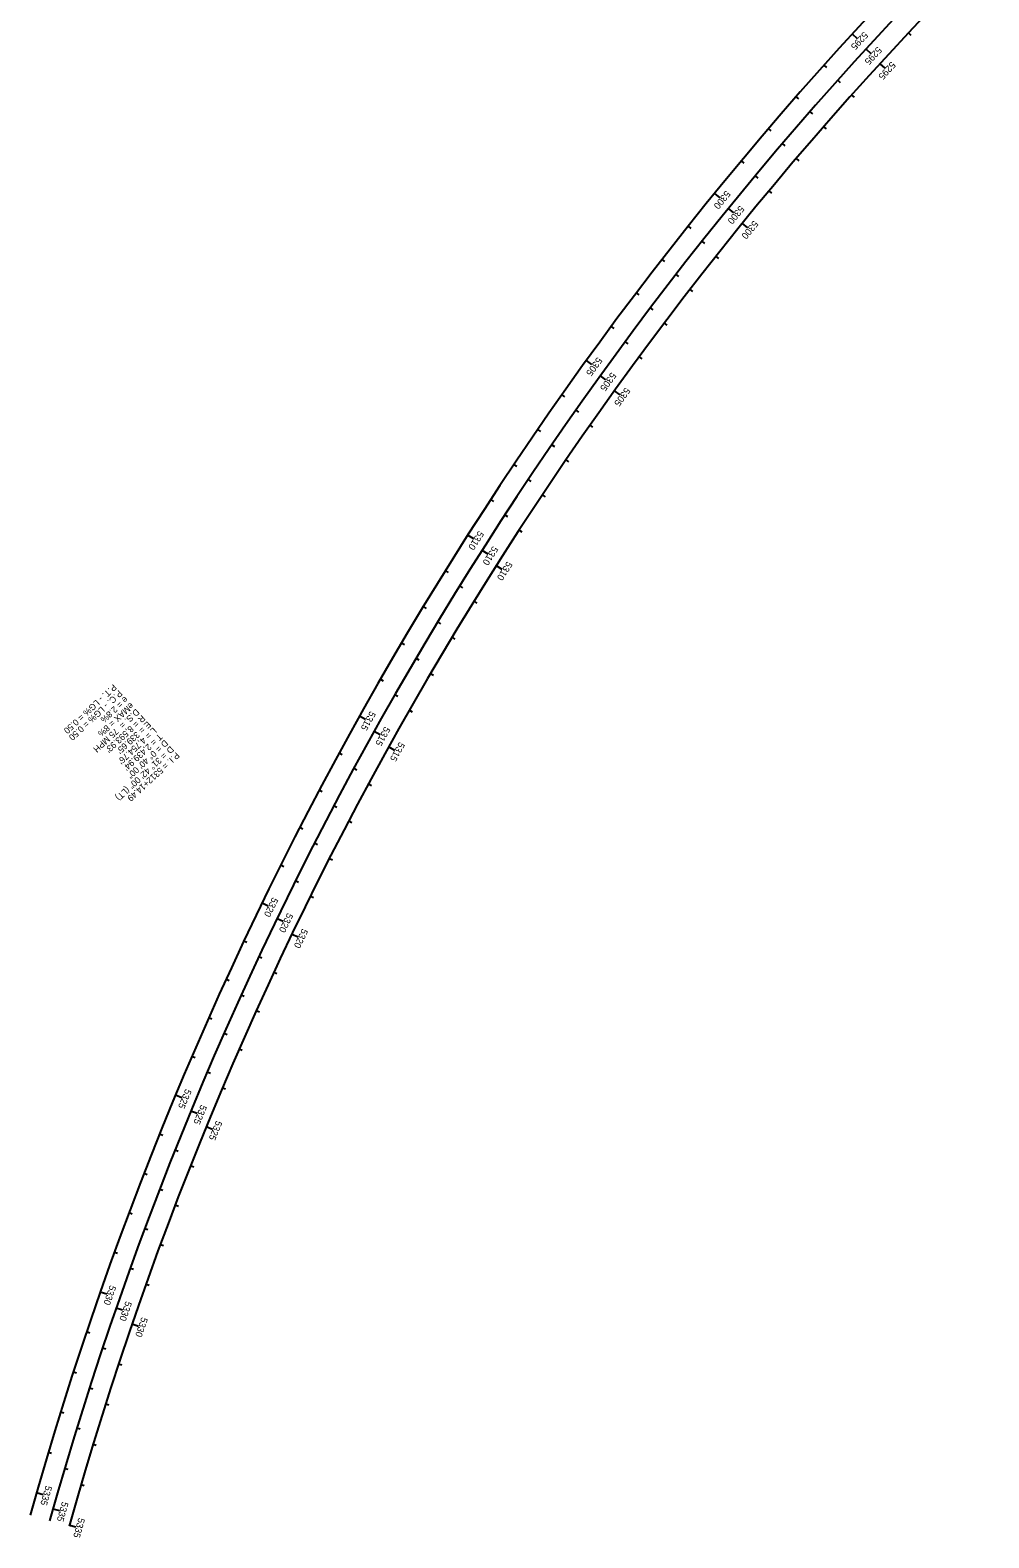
# Model space of a CAD drawing. Extents: x 2161211 to 2175594, y 601812 to 617732.
# Drawn here: x 2161211 to 2163485, y 601812 to 605389 of the extents above; entities that cross this region are included whole.
import ezdxf

# ---------------------------------------------------------------- set-up
doc = ezdxf.new("R2010")
doc.units = 0
for name, color, linetype in [('RD_HC_Cl', 7, 'Continuous'), ('RD_HC_Data', 7, 'Continuous'), ('RD_HC_Data_Tic', 7, 'Continuous'), ('RD_HC_TX_Sta50', 7, 'Continuous')]:
    doc.layers.add(name, color=color, linetype=linetype)

msp = doc.modelspace()

# ---------------------------------------------------------------- linework, layer by layer
at = {"layer": 'RD_HC_Cl'}
for radius in [8641.9, 8593.9, 8545.9]:
    msp.add_arc((2169535, 599544.7), radius, 135.07107, 164.41949, dxfattribs=at)
at = {"layer": 'RD_HC_Data_Tic'}
for p, q in [((2163160.5, 605379.9), (2163172.3, 605369.1)), ((2163293.8, 605382.6), (2163299.6, 605377.1)), ((2163193.2, 605344.5), (2163205, 605333.7)), ((2163093.4, 605305.7), (2163099.4, 605300.4)), ((2163225.9, 605309.1), (2163237.7, 605298.3)), ((2163126.2, 605270.3), (2163132.1, 605265)), ((2163027.2, 605230.8), (2163033.2, 605225.6)), ((2163158.9, 605234.9), (2163164.9, 605229.6)), ((2163060, 605195.4), (2163066, 605190.1)), ((2162961.9, 605155.1), (2162967.9, 605149.9)), ((2163092.7, 605159.9), (2163098.8, 605154.7)), ((2162994.7, 605119.6), (2163000.8, 605114.4)), ((2162897.4, 605078.7), (2162903.5, 605073.6)), ((2163027.5, 605084.1), (2163033.6, 605079)), ((2162930.2, 605043.2), (2162936.4, 605038)), ((2162833.8, 605001.5), (2162846.2, 604991.4)), ((2162963.1, 605007.6), (2162969.3, 605002.5)), ((2162866.7, 604965.9), (2162879.1, 604955.8)), ((2162771.1, 604923.6), (2162777.4, 604918.6)), ((2162899.6, 604930.3), (2162912.1, 604920.3)), ((2162804.1, 604888), (2162810.3, 604883)), ((2162837.1, 604852.3), (2162843.3, 604847.4)), ((2162709.3, 604845), (2162715.6, 604840.1)), ((2162742.4, 604809.3), (2162748.7, 604804.4)), ((2162648.4, 604765.7), (2162654.8, 604760.8)), ((2162775.4, 604773.6), (2162781.8, 604768.7)), ((2162681.6, 604729.9), (2162687.9, 604725.1)), ((2162588.5, 604685.6), (2162594.9, 604680.9)), ((2162714.7, 604694.1), (2162721.1, 604689.3)), ((2162621.7, 604649.8), (2162628.1, 604645)), ((2162529.5, 604604.9), (2162542.4, 604595.5)), ((2162654.9, 604614), (2162661.4, 604609.2)), ((2162562.8, 604569), (2162575.7, 604559.7)), ((2162596.1, 604533.1), (2162609.1, 604523.8)), ((2162471.4, 604523.5), (2162477.9, 604518.9)), ((2162504.8, 604487.5), (2162511.3, 604482.9)), ((2162414.2, 604441.4), (2162420.8, 604436.9)), ((2162538.2, 604451.6), (2162544.7, 604447)), ((2162447.7, 604405.4), (2162454.3, 604400.9)), ((2162358.1, 604358.7), (2162364.7, 604354.2)), ((2162481.2, 604369.4), (2162487.8, 604364.9)), ((2162391.7, 604322.6), (2162398.3, 604318.2)), ((2162425.3, 604286.5), (2162431.9, 604282.1)), ((2162302.8, 604275.3), (2162309.5, 604271)), ((2162336.5, 604239.2), (2162343.2, 604234.8)), ((2162248.6, 604191.3), (2162262.1, 604182.7)), ((2162370.3, 604203), (2162377, 604198.6)), ((2162282.4, 604155.1), (2162295.9, 604146.5)), ((2162195.3, 604106.7), (2162202.1, 604102.5)), ((2162316.3, 604118.8), (2162329.8, 604110.3)), ((2162229.3, 604070.4), (2162236.1, 604066.2)), ((2162263.2, 604034.1), (2162270, 604029.9)), ((2162143, 604021.5), (2162149.8, 604017.3)), ((2162177.1, 603985.1), (2162183.9, 603980.9)), ((2162091.7, 603935.6), (2162098.6, 603931.6)), ((2162211.2, 603948.7), (2162218, 603944.5)), ((2162125.9, 603899.2), (2162132.8, 603895.1)), ((2162041.4, 603849.2), (2162048.3, 603845.2)), ((2162160.2, 603862.7), (2162167.1, 603858.6)), ((2162075.8, 603812.7), (2162082.7, 603808.7)), ((2162110.1, 603776.1), (2162117.1, 603772.1)), ((2161992.1, 603762.2), (2162006, 603754.4)), ((2162026.6, 603725.6), (2162040.6, 603717.8)), ((2161943.8, 603674.6), (2161950.8, 603670.8)), ((2162061.1, 603688.9), (2162075.1, 603681.2)), ((2161978.5, 603637.9), (2161985.5, 603634.1)), ((2162013.2, 603601.2), (2162020.2, 603597.4)), ((2161896.5, 603586.5), (2161903.6, 603582.8)), ((2161931.3, 603549.7), (2161938.4, 603546)), ((2161850.2, 603497.9), (2161857.4, 603494.2)), ((2161966.2, 603512.9), (2161973.3, 603509.2)), ((2161885.3, 603461), (2161892.4, 603457.3)), ((2161920.3, 603424), (2161927.4, 603420.4)), ((2161805, 603408.7), (2161812.2, 603405.1)), ((2161840.2, 603371.7), (2161847.4, 603368.1)), ((2161760.8, 603319), (2161775.2, 603312)), ((2161875.4, 603334.7), (2161882.6, 603331.1)), ((2161796.2, 603281.9), (2161810.6, 603274.9)), ((2161831.6, 603244.8), (2161846, 603237.9)), ((2161717.7, 603228.8), (2161724.9, 603225.4)), ((2161753.2, 603191.6), (2161760.5, 603188.2)), ((2161675.6, 603138.1), (2161682.8, 603134.7)), ((2161788.8, 603154.4), (2161796.1, 603151)), ((2161711.3, 603100.8), (2161718.6, 603097.5)), ((2161747.1, 603063.5), (2161754.4, 603060.2)), ((2161634.5, 603046.9), (2161641.8, 603043.6)), ((2161670.5, 603009.5), (2161677.8, 603006.3)), ((2161594.5, 602955.2), (2161601.9, 602952.1)), ((2161706.5, 602972.1), (2161713.8, 602968.9)), ((2161630.7, 602917.8), (2161638.1, 602914.6)), ((2161555.6, 602863.1), (2161570.4, 602857)), ((2161666.9, 602880.3), (2161674.3, 602877.2)), ((2161592, 602825.6), (2161606.8, 602819.5)), ((2161628.4, 602788), (2161643.2, 602781.9)), ((2161517.7, 602770.6), (2161525.1, 602767.6)), ((2161554.3, 602732.9), (2161561.8, 602730)), ((2161480.9, 602677.6), (2161488.4, 602674.7)), ((2161591, 602695.3), (2161598.5, 602692.3)), ((2161517.8, 602639.9), (2161525.2, 602637)), ((2161554.7, 602602.1), (2161562.2, 602599.2)), ((2161445.2, 602584.2), (2161452.7, 602581.4)), ((2161482.3, 602546.4), (2161489.8, 602543.6)), ((2161410.6, 602490.4), (2161418.1, 602487.6)), ((2161519.5, 602508.5), (2161527, 602505.7)), ((2161447.9, 602452.5), (2161455.5, 602449.7)), ((2161377, 602396.2), (2161392.2, 602390.9)), ((2161485.3, 602414.5), (2161492.9, 602411.8)), ((2161414.6, 602358.2), (2161429.8, 602352.9)), ((2161452.3, 602320.1), (2161467.4, 602314.9)), ((2161344.6, 602301.6), (2161352.2, 602299)), ((2161382.5, 602263.5), (2161390, 602260.9)), ((2161313.2, 602206.6), (2161320.9, 602204.2)), ((2161420.4, 602225.4), (2161428, 602222.9)), ((2161351.4, 602168.4), (2161359, 602166)), ((2161283, 602111.3), (2161290.6, 602108.9)), ((2161389.6, 602130.2), (2161397.2, 602127.8)), ((2161321.4, 602073), (2161329, 602070.7)), ((2161359.9, 602034.7), (2161367.5, 602032.4)), ((2161253.9, 602015.6), (2161261.5, 602013.4)), ((2161292.5, 601977.3), (2161300.2, 601975)), ((2161225.8, 601919.7), (2161241.2, 601915.3)), ((2161331.3, 601938.9), (2161339, 601936.7)), ((2161264.8, 601881.2), (2161280.2, 601876.9)), ((2161303.8, 601842.8), (2161319.3, 601838.5))]:
    msp.add_line(p, q, dxfattribs=at)

# ---------------------------------------------------------------- texts
at = {"layer": 'RD_HC_Data'}
for s, p in [('P.T. - LG% = 0.50', (2161407.4, 603838.7)), ('P.C. - LG% = 0.50', (2161421, 603824.1)), ('D.S. =  75 MPH', (2161461.7, 603780)), ('eMAX = 8%', (2161448.1, 603794.7)), ('e = 2.8%', (2161434.6, 603809.4)), ("R = 8,593.93'", (2161475.3, 603765.3)), ("E = 339.65'", (2161488.8, 603750.6)), ("L = 4,754.76'", (2161502.4, 603735.9)), ("T = 2,439.94'", (2161516, 603721.2)), ('D = 0° 40\' 00"', (2161529.6, 603706.5)), ('    = 31° 42\' 00" (LT)', (2161543.1, 603691.8)), ('P.I. = 5312+14.49', (2161556.7, 603677.1)), ('D', (2161543.1, 603691.8))]:
    msp.add_text(s, height=15, rotation=222.7195, dxfattribs=at).set_placement(p)
at = {"layer": 'RD_HC_TX_Sta50'}
for s, rotation, p in [('5295', 227.5292, (2163188.1, 605386.3)), ('5295', 227.556, (2163220.7, 605350.9)), ('5295', 227.5832, (2163253.4, 605315.5)), ('5300', 230.8442, (2162860.9, 605009.5)), ('5300', 230.8895, (2162893.8, 604974)), ('5300', 230.9354, (2162926.8, 604938.4)), ('5305', 234.1592, (2162556.1, 604614.4)), ('5305', 234.223, (2162589.3, 604578.5)), ('5305', 234.2877, (2162622.6, 604542.7)), ('5310', 237.4741, (2162274.6, 604202.4)), ('5310', 237.5565, (2162308.4, 604166.2)), ('5310', 237.6399, (2162342.3, 604130)), ('5315', 240.7891, (2162017.4, 603774.7)), ('5315', 240.8901, (2162051.9, 603738.1)), ('5315', 240.9921, (2162086.4, 603701.5)), ('5320', 244.1041, (2161785.4, 603333)), ('5320', 244.2236, (2161820.8, 603296)), ('5320', 244.3443, (2161856.1, 603258.9)), ('5325', 247.4191, (2161579.3, 602878.5)), ('5325', 247.5571, (2161615.7, 602841)), ('5325', 247.6966, (2161652.1, 602803.5)), ('5330', 250.7341, (2161399.9, 602412.9)), ('5330', 250.8906, (2161437.4, 602375)), ('5330', 251.0488, (2161475, 602337)), ('5335', 254.0491, (2161247.6, 601937.6)), ('5335', 254.2241, (2161286.5, 601899.3)), ('5335', 254.401, (2161325.5, 601860.9))]:
    msp.add_text(s, height=16, rotation=rotation, dxfattribs=at).set_placement(p)

doc.saveas('drawing.dxf')
